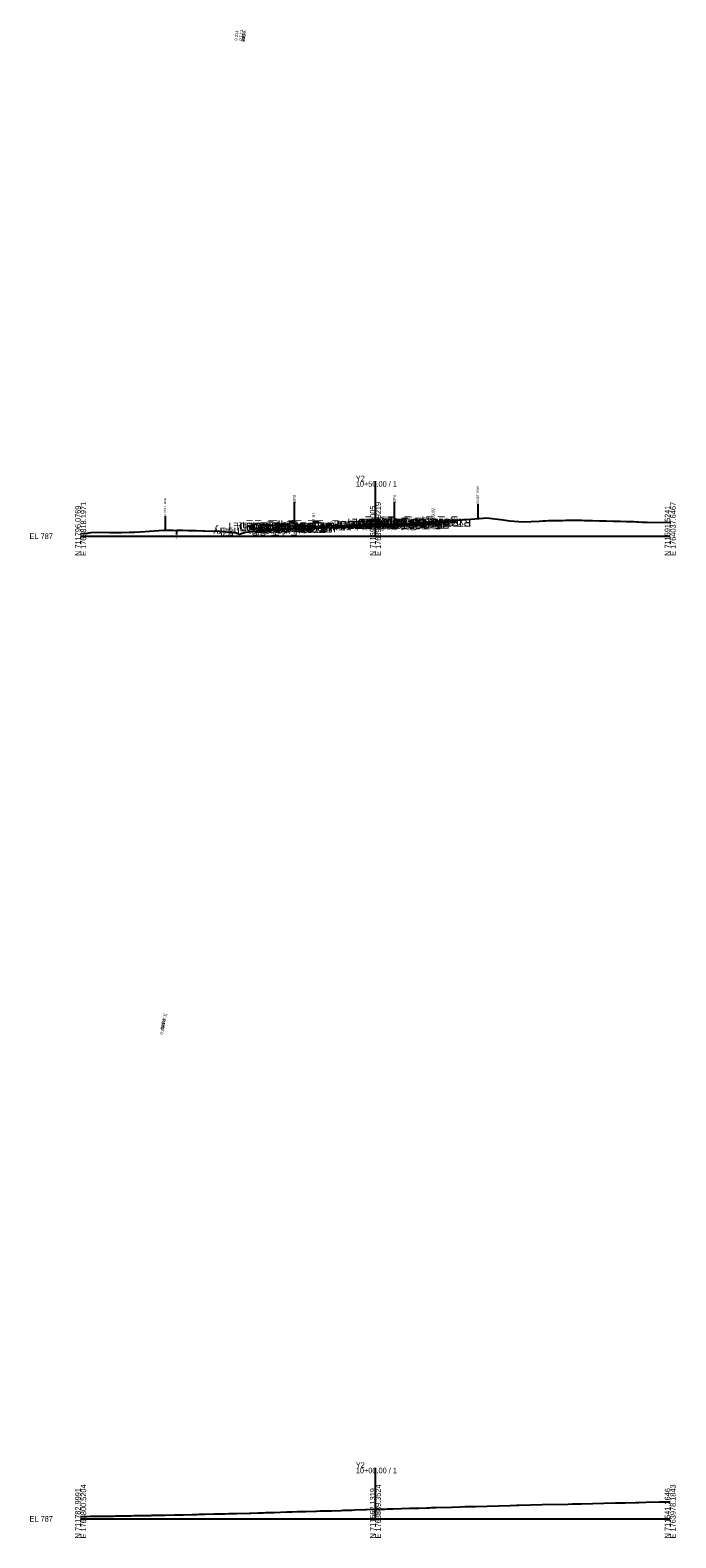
# Model space of a CAD drawing. Extents: x -26 to 1764011, y -10 to 712381.
# Drawn here: x -26 to 303, y -10 to 758 of the extents above; entities that cross this region are included whole.
import ezdxf

# ---------------------------------------------------------------- set-up
doc = ezdxf.new("R2010")
doc.units = 0
for name, color, linetype in [('Default', 7, 'Continuous'), ('Exist Cross Section Cell', 7, 'Continuous'), ('Exist XS Center Line Elevation Label', 7, 'Continuous'), ('Exist XS Ground Line', 7, 'Continuous'), ('Old_Level_10', 7, 'Continuous'), ('Prop CMT Conc Surface', 7, 'Continuous'), ('Prop CMT Concrete Structures', 7, 'Continuous'), ('Prop CMT Pvmt Course 1', 7, 'Continuous'), ('Prop CMT Pvmt Course 1 CG', 7, 'Continuous'), ('Prop CMT Pvmt Course 2', 7, 'Continuous'), ('Prop CMT Pvmt Course 3', 7, 'Continuous'), ('Prop CMT Pvmt Surface', 7, 'Continuous'), ('Prop CMT Slope Grass', 7, 'Continuous'), ('Prop CMT Subgrade Earthwork', 7, 'Continuous'), ('Prop XS Earthwork Shape', 7, 'Continuous'), ('Prop XS Hydro Elevations', 7, 'Continuous'), ('Prop XS SE Text', 7, 'Continuous'), ('Prop XS Shear Point Element', 7, 'Continuous'), ('Prop XS Side Slope Text', 7, 'Continuous'), ('Scratch_Level_7', 7, 'Continuous')]:
    doc.layers.add(name, color=color, linetype=linetype)

msp = doc.modelspace()

# ---------------------------------------------------------------- linework, layer by layer
at = {"layer": 'Exist Cross Section Cell'}
for p, q in [((150, 500), (150, 528.01)), ((0, 500), (150, 500)), ((150, 500), (300, 500)), ((150, 0), (150, 25.98)), ((0, 0), (150, 0)), ((150, 0), (300, 0))]:
    msp.add_line(p, q, dxfattribs=at)
at = {"layer": 'Exist XS Ground Line'}
for points in [[(0, 501.33), (3.48, 501.54), (5.25, 501.91), (8.72, 502.11), (14.86, 501.92), (17.65, 501.96), (20.74, 501.89), (24.74, 502.04), (27.33, 502), (32.65, 502.4), (42.11, 503.04), (45.37, 503.04), (47.15, 503.13), (48.71, 503), (49.05, 503.03), (49.68, 503.04), (51.08, 503.03), (52.02, 503.02), (54.74, 502.94), (55.1, 502.94), (55.44, 502.93), (58.86, 502.86), (62.27, 502.76), (62.77, 502.75), (68.46, 502.63), (68.78, 502.84), (77.73, 501.98), (78.65, 501.92), (80.89, 500.98), (83.94, 502.14), (99.79, 503.48), (103.84, 503.83), (110.56, 504.09), (118.56, 504.11), (121.8, 504.25), (131.6, 504.56), (132.6, 504.59), (133.5, 504.63), (145.97, 505.25), (148.17, 505.35), (150, 505.43), (159.64, 505.83), (162.83, 505.96), (168.26, 506.24), (173.31, 506.75), (177.5, 507.12), (186.99, 507.86), (191.35, 508.12), (198.58, 508.68), (204.76, 509.18), (206.66, 509.34), (215.03, 508.39), (218.32, 507.88), (225.24, 507.26), (233.37, 507.74), (234.98, 507.84), (235.45, 507.88), (235.77, 507.9), (236.57, 507.93), (238.07, 507.96), (239.99, 507.98), (241.74, 508), (243.41, 508.02), (245.4, 508.07), (246.83, 508.12), (249.07, 508.16), (250.24, 508.16), (251.68, 508.19), (252.17, 508.18), (253.66, 508.15), (254.98, 508.1), (256.4, 508.05), (257.08, 508.02), (260.07, 507.96), (260.5, 507.95), (263.91, 507.87), (265.6, 507.8), (267.4, 507.78), (271.07, 507.69), (274.17, 507.64), (274.74, 507.63), (277.58, 507.57), (278.4, 507.55), (281, 507.46), (281.52, 507.44), (282.98, 507.31), (283.77, 507.27), (285.67, 507.23), (288.23, 507.19), (299.65, 507.06), (300, 507.06)], [(0, 1.2), (1.23, 1.21), (1.77, 1.21), (2.17, 1.22), (4.77, 1.26), (7.21, 1.29), (12.44, 1.35), (13.9, 1.37), (14.58, 1.38), (16.63, 1.41), (17.73, 1.45), (22.36, 1.54), (25.64, 1.59), (26.99, 1.61), (28.19, 1.63), (32.25, 1.69), (35, 1.75), (35.75, 1.76), (36.3, 1.77), (38.27, 1.8), (39.4, 1.84), (39.89, 1.85), (41.75, 1.88), (42.94, 1.9), (47.67, 2.01), (48.71, 2.02), (51.6, 2.09), (52.08, 2.1), (56.75, 2.19), (59.23, 2.24), (60.33, 2.28), (61.12, 2.3), (63.3, 2.35), (67.79, 2.45), (71.86, 2.53), (73, 2.55), (73.53, 2.57), (75.38, 2.62), (76.63, 2.68), (78.47, 2.71), (79.54, 2.75), (85.94, 2.93), (86.71, 2.95), (90.32, 3.05), (92.94, 3.11), (94.1, 3.15), (95.25, 3.19), (98.42, 3.28), (104.87, 3.47), (106.77, 3.53), (107.66, 3.56), (110.13, 3.63), (110.92, 3.65), (111.92, 3.65), (113.35, 3.72), (114.63, 3.74), (119.43, 3.9), (120.07, 3.92), (121.83, 3.98), (123.81, 4.03), (125.49, 4.06), (126.36, 4.1), (127.71, 4.13), (132.48, 4.27), (133.54, 4.31), (136.17, 4.38), (137.11, 4.4), (138.21, 4.45), (139.32, 4.48), (144.89, 4.68), (145.24, 4.69), (150, 4.83), (151.67, 4.88), (154.74, 4.96), (156.37, 5.01), (157.38, 5.04), (159.07, 5.1), (167.28, 5.35), (172.03, 5.49), (176.07, 5.61), (177.62, 5.66), (178.45, 5.68), (180.66, 5.75), (188.68, 5.99), (193.18, 6.12), (195.68, 6.2), (196.4, 6.21), (196.95, 6.23), (197.79, 6.25), (200.83, 6.34), (218.62, 6.82), (221.8, 6.9), (222.87, 6.93), (234.75, 7.21), (248.12, 7.53), (250.33, 7.59), (251.4, 7.61), (253.24, 7.66), (253.58, 7.67), (254.92, 7.7), (272.04, 8.07), (276.99, 8.19), (282.36, 8.3), (283.12, 8.31), (283.94, 8.34), (287.6, 8.42), (294.36, 8.55), (295.18, 8.56), (296.92, 8.57), (297.42, 8.59), (300, 8.66)]]:
    msp.add_lwpolyline(points, dxfattribs=at)
at = {"layer": 'Old_Level_10'}
for p, q in [((202.08, 516.37), (202.08, 508.97)), ((42.92, 510.42), (42.92, 503.02)), ((48.71, 503), (48.71, 500.95))]:
    msp.add_line(p, q, dxfattribs=at)
at = {"layer": 'Prop CMT Conc Surface'}
for points in [[(177.32, 506.91), (179.32, 506.89)], [(179.32, 506.89), (179.32, 507.39), (179.82, 507.39)], [(118.57, 504.81), (118.56, 505.31), (118.06, 505.31)], [(120.56, 504.96), (118.57, 504.81)]]:
    msp.add_lwpolyline(points, dxfattribs=at)
at = {"layer": 'Prop CMT Concrete Structures'}
for points in [[(177.32, 506.91), (179.32, 506.89), (179.32, 507.39), (179.82, 507.39)], [(179.82, 507.39), (179.82, 506.41), (177.32, 506.32)], [(177.32, 506.32), (177.32, 506.91)], [(120.56, 504.96), (118.57, 504.81), (118.56, 505.31), (118.06, 505.31)], [(118.06, 505.31), (118.07, 504.29), (120.56, 504.38)], [(120.56, 504.38), (120.56, 504.96)]]:
    msp.add_lwpolyline(points, dxfattribs=at)
at = {"layer": 'Prop CMT Pvmt Course 1'}
for points in [[(150, 505.97), (177.32, 506.91)], [(177.32, 506.66), (150, 505.72)], [(177.32, 506.91), (177.32, 506.66)], [(150, 505.97), (120.56, 504.96)], [(120.56, 504.71), (150, 505.72)], [(120.56, 504.96), (120.56, 504.71)], [(150, 505.72), (150, 505.97)]]:
    msp.add_lwpolyline(points, dxfattribs=at)
msp.add_lwpolyline([(150, 505.72), (150, 505.72), (150, 505.72), (150, 505.72)], close=True, dxfattribs=at)
at = {"layer": 'Prop CMT Pvmt Course 1 CG'}
for points in [[(177.32, 506.32), (179.82, 506.41), (180.14, 506.09)], [(120.56, 504.38), (118.07, 504.29), (117.72, 503.94)], [(117.72, 503.94), (120.56, 504.04)], [(120.56, 504.04), (120.56, 504.38)], [(177.32, 505.99), (177.32, 506.32)], [(180.14, 506.09), (177.32, 505.99)]]:
    msp.add_lwpolyline(points, dxfattribs=at)
at = {"layer": 'Prop CMT Pvmt Course 2'}
for points in [[(150, 505.72), (177.32, 506.66)], [(177.32, 506.66), (177.32, 506.32)], [(150, 505.72), (120.56, 504.71)], [(120.56, 504.38), (150, 505.39)], [(120.56, 504.71), (120.56, 504.38)], [(177.32, 506.32), (150, 505.39)], [(150, 505.39), (150, 505.72)]]:
    msp.add_lwpolyline(points, dxfattribs=at)
at = {"layer": 'Prop CMT Pvmt Course 3'}
for points in [[(150, 505.39), (120.56, 504.38)], [(120.56, 504.04), (150, 505.05)], [(120.56, 504.38), (120.56, 504.04)], [(150, 505.39), (177.32, 506.32)], [(177.32, 505.99), (150, 505.05)], [(150, 505.05), (150, 505.39)], [(177.32, 506.32), (177.32, 505.99)]]:
    msp.add_lwpolyline(points, dxfattribs=at)
at = {"layer": 'Prop CMT Pvmt Surface'}
for points in [[(150, 505.97), (177.32, 506.91)], [(150, 505.97), (120.56, 504.96)]]:
    msp.add_lwpolyline(points, dxfattribs=at)
at = {"layer": 'Prop CMT Slope Grass'}
for p, q in [((189.32, 507.58), (191.55, 508.14)), ((118.06, 505.31), (108.81, 504.73)), ((108.81, 504.73), (108.81, 504.02))]:
    msp.add_line(p, q, dxfattribs=at)
msp.add_lwpolyline([(179.82, 507.39), (189.32, 507.58)], dxfattribs=at)
at = {"layer": 'Prop CMT Subgrade Earthwork'}
for points in [[(177.32, 505.99), (180.14, 506.09), (181.48, 507.43)], [(120.56, 504.04), (117.72, 503.94), (116.46, 505.21)], [(150, 505.05), (120.56, 504.04)], [(150, 505.05), (177.32, 505.99)]]:
    msp.add_lwpolyline(points, dxfattribs=at)
at = {"layer": 'Prop XS Earthwork Shape'}
for points in [[(181.36, 507.42), (181.48, 507.43), (180.14, 506.09), (177.32, 505.99), (150, 505.05), (120.56, 504.04), (117.72, 503.94), (117.56, 504.11), (118.56, 504.11), (121.8, 504.25), (131.6, 504.56), (132.6, 504.59), (133.5, 504.63), (145.97, 505.25), (148.17, 505.35), (150, 505.43), (159.64, 505.83), (162.83, 505.96), (168.26, 506.24), (173.31, 506.75), (173.63, 506.78), (177.32, 506.91), (179.32, 506.89), (179.32, 507.27)], [(173.63, 506.78), (177.32, 506.91), (179.32, 506.89), (179.32, 507.27), (177.5, 507.12)], [(181.48, 507.43), (189.32, 507.58), (191.55, 508.14), (191.35, 508.12), (186.99, 507.86), (181.36, 507.42)], [(108.81, 504.02), (110.56, 504.09), (117.56, 504.11), (116.46, 505.21), (108.81, 504.73)]]:
    msp.add_lwpolyline(points, close=True, dxfattribs=at)
at = {"layer": 'Prop XS Shear Point Element'}
for p, q in [((108.81, 504.73), (108.81, 517.26)), ((159.69, 506.3), (159.69, 517.26))]:
    msp.add_line(p, q, dxfattribs=at)

# ---------------------------------------------------------------- texts
at = {"layer": 'Default'}
for p in [(0, 500), (0, 0)]:
    msp.add_text('-', height=0.0001, dxfattribs=at).set_placement(p)
at = {"layer": 'Exist Cross Section Cell'}
for s, p in [('Y2', (140, 528.01)), ('10+50.00 / 1', (140, 525.21)), ('EL 787', (-26, 498.6)), ('Y2', (140, 25.98)), ('10+00.00 / 1', (140, 23.18)), ('EL 787', (-26, -1.4))]:
    msp.add_text(s, height=2.8, dxfattribs=at).set_placement(p)
for s, p in [('N 711796.0769', (0, 490)), ('E 1763818.1971', (2.8, 490)), ('N 711693.8005', (150, 490)), ('E 1763927.9219', (152.8, 490)), ('N 711591.5241', (300, 490)), ('E 1764037.6467', (302.8, 490)), ('N 711782.9991', (0, -10)), ('E 1763800.5204', (2.8, -10)), ('N 711662.1319', (150, -10)), ('E 1763889.3524', (152.8, -10)), ('N 711541.2646', (300, -10)), ('E 1763978.1843', (302.8, -10))]:
    msp.add_text(s, height=2.8, rotation=90, dxfattribs=at).set_placement(p)
at = {"layer": 'Exist XS Center Line Elevation Label'}
for s, p in [('792.43', (147.88, 503.43)), ('791.83', (148, 2.83))]:
    msp.add_text(s, height=1, dxfattribs=at).set_placement(p)
at = {"layer": 'Old_Level_10'}
for s, height, p in [('EXIST. R/W', 1.181, (202.67, 516.67)), ('EXIST. R/W', 1.181, (43.51, 510.73)), ('EOP', 0.787, (49.1, 498.55))]:
    msp.add_text(s, height=height, rotation=90, dxfattribs=at).set_placement(p)
at = {"layer": 'Prop XS Hydro Elevations'}
for s, p in [('791.81', (119.32, 505.81)), ('793.89', (180.07, 507.89))]:
    msp.add_text(s, height=1.5, rotation=90, dxfattribs=at).set_placement(p)
at = {"layer": 'Prop XS SE Text'}
for s, rotation, p in [('9.314', 83.87207, (79.75, 752.14)), ('0.034', 1.96366, (127.15, 506.19)), ('0.034', 1.96366, (153.35, 507.08))]:
    msp.add_text(s, height=1.5, rotation=rotation, dxfattribs=at).set_placement(p)
at = {"layer": 'Prop XS Shear Point Element'}
for s, p in [('SP3', (109.59, 517.01)), ('SP4', (160.46, 517.02))]:
    msp.add_text(s, height=1.5, rotation=90, dxfattribs=at).set_placement(p)
at = {"layer": 'Prop XS Side Slope Text'}
for s, rotation, p in [('0.11:1', 83.72064, (82, 752.08)), ('0.11:1', 83.62534, (83.23, 751.77)), ('895%', 83.62534, (83.46, 751.53)), ('0:1', 83.62534, (83.61, 752.86)), ('4:1', 14.03624, (188.21, 507.91)), ('0:1 [RUN:1]', 80.22813, (41.91, 246.29)), ('0.17:1', 80.22813, (42.1, 248.85)), ('581%', 80.22813, (42.37, 248.95))]:
    msp.add_text(s, height=1.5, rotation=rotation, dxfattribs=at).set_placement(p)
at = {"layer": 'Scratch_Level_7'}
for s, p in [('LT_Sub_Trench_Out_DLT', (137.37, 506.97)), ('LT_CSLP_Pnt', (114.97, 507.12)), ('LT_CG1_Shelf_Out', (129.83, 505.91)), ('LT_CG_Top_BOC', (128, 506.93)), ('LT_CG_Bot_BOC', (127.56, 505.91)), ('LT_CG_Top_Face', (129.41, 506.93)), ('LT_CG_Top_Gut', (127.46, 506.43)), ('LT_Sub_OEOP', (124.93, 505.57)), ('LT_PV1_OEOT', (127.22, 506.58)), ('LT_PV2_OEOT', (128.23, 506.33)), ('LT_PV3_OEOT', (128.26, 506)), ('LT_Sub_OEOT', (127.7, 505.67)), ('LT_CG_Bot_IE', (127.57, 506)), ('RT_PV1_OEEOP', (170.2, 507.72)), ('LT_PV1_OEEOP', (169.7, 507.72)), ('RT_PV2_OEEOP', (171.21, 507.72)), ('RT_PV3_OEEOP', (171.24, 507.39)), ('RT_Sub_OEEOP', (170.67, 507.05)), ('LT_PV2_OEEOP', (170.71, 507.72)), ('LT_PV3_OEEOP', (170.74, 507.39)), ('LT_Sub_OEEOP', (170.17, 507.05)), ('RT_PV1_IEEOP', (169.32, 507.72)), ('LT_PV1_IEEOP', (168.82, 507.72)), ('RT_PV2_IEEOP', (170.33, 507.72)), ('LT_PV2_IEEOP', (169.82, 507.72)), ('RT_Sub_Trench_Out_DLT', (198.69, 508.9)), ('PV1_PGL', (160.68, 507.97)), ('PV2_PGL', (161.68, 507.72)), ('RT_CG1_Shelf_Out', (187.74, 507.88)), ('RT_CG_Top_BOC', (185.92, 508.87)), ('RT_CG_Top_Face', (186.33, 508.87)), ('RT_PV1_OEOT', (180.14, 508.38)), ('RT_CG_Bot_BOC', (185.47, 507.88)), ('RT_CG_Top_Gut', (184.37, 508.37)), ('RT_PV2_OEOT', (181.15, 508.13)), ('RT_PV3_OEOT', (181.18, 507.8)), ('RT_Sub_OEOT', (180.61, 507.46)), ('RT_CG_Bot_IE', (180.49, 507.8)), ('RT_Sub_OEOP', (183.51, 507.56)), ('Exterior Boundary', (198.5, 508.88)), ('RT_CSLP_Pnt', (191.89, 509.06)), ('RT_Slope_Fill', (192.51, 508.88)), ('Exterior Boundary', (110.29, 504.36)), ('LT_Slope_Fill', (103.79, 504.36))]:
    msp.add_text(s, height=4, rotation=180, dxfattribs=at).set_placement(p)

doc.saveas('drawing.dxf')
